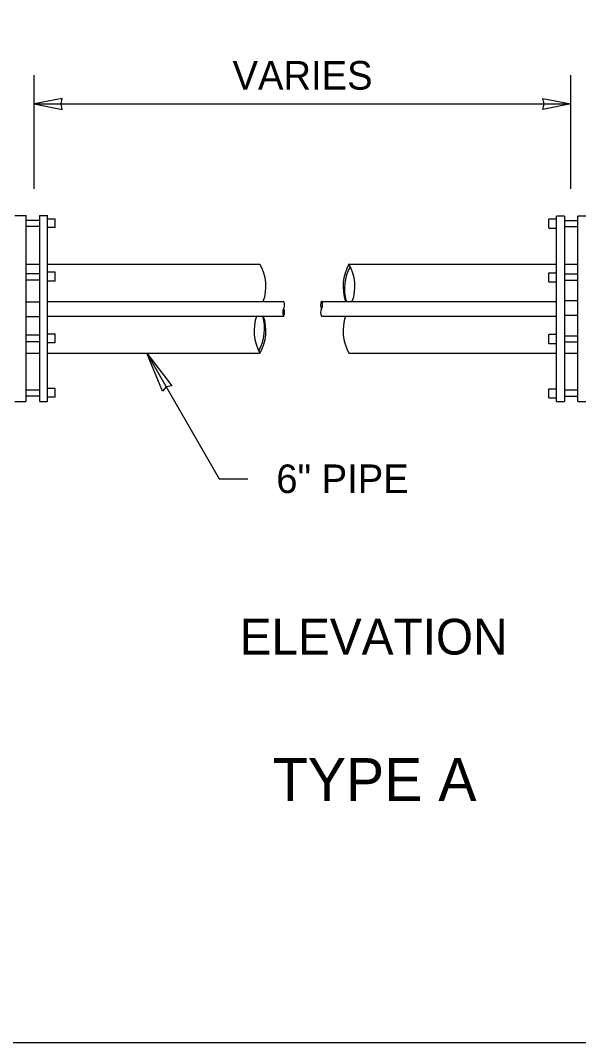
# Model space of a CAD drawing. Extents: x 99862 to 103151, y 100000 to 102076.
# Drawn here: x 100475 to 100788, y 100000 to 100572 of the extents above; entities that cross this region are included whole.
import ezdxf

# ---------------------------------------------------------------- set-up
doc = ezdxf.new("R2010")
doc.units = 0
for name, color, linetype in [('Level 1', 7, 'Continuous'), ('Level 15', 7, 'Continuous'), ('Level 18', 7, 'Continuous'), ('Level 20', 7, 'Continuous'), ('Level 6', 7, 'Continuous')]:
    doc.layers.add(name, color=color, linetype=linetype)

msp = doc.modelspace()

# ---------------------------------------------------------------- linework, layer by layer
at = {"layer": 'Level 1'}
msp.add_lwpolyline([(99862, 99999.5), (103151, 99999.5), (103151, 102075.5), (99862, 102075.5)], close=True, dxfattribs=at)
at = {"layer": 'Level 15'}
for p, q in [((100483.01, 100477.71), (100483.01, 100541.21)), ((100783.78, 100477.71), (100783.78, 100541.21)), ((100483.01, 100525.21), (100783.78, 100525.21)), ((100546.06, 100385.62), (100586.68, 100315.26)), ((100586.68, 100315.26), (100602.68, 100315.26))]:
    msp.add_line(p, q, dxfattribs=at)
for points in [[(100483.01, 100525.21), (100498.73, 100522.13), (100498, 100525.21), (100498.73, 100528.29)], [(100783.78, 100525.21), (100768.06, 100522.13), (100768.79, 100525.21), (100768.06, 100528.29)], [(100546.06, 100385.62), (100560.06, 100367.34), (100556.94, 100366.77), (100554.89, 100364.36)]]:
    msp.add_lwpolyline(points, close=True, dxfattribs=at)
at = {"layer": 'Level 18'}
for p, q in [((100472.06, 100462.71), (100478.43, 100462.71)), ((100478.43, 100358.76), (100478.43, 100462.71)), ((100478.43, 100460.16), (100485.89, 100460.16)), ((100485.89, 100462.71), (100485.89, 100358.76)), ((100485.89, 100462.71), (100490.41, 100462.71)), ((100490.41, 100358.76), (100490.41, 100462.71)), ((100490.41, 100460.9), (100494.66, 100460.9)), ((100494.66, 100455.92), (100494.66, 100460.9)), ((100775.52, 100460.58), (100771.41, 100460.58)), ((100771.41, 100455.62), (100771.41, 100460.58)), ((100775.67, 100358.46), (100775.67, 100462.4)), ((100780.17, 100462.4), (100775.67, 100462.4)), ((100780.17, 100462.4), (100780.17, 100358.46)), ((100780.17, 100459.87), (100787.63, 100459.87)), ((100787.63, 100358.46), (100787.63, 100462.4)), ((100794.02, 100462.4), (100787.63, 100462.4)), ((100478.43, 100456.67), (100485.89, 100456.67)), ((100494.66, 100455.92), (100490.41, 100455.92)), ((100771.41, 100455.62), (100775.52, 100455.62)), ((100787.63, 100456.36), (100780.17, 100456.36)), ((100478.43, 100430.18), (100485.89, 100430.18)), ((100478.43, 100426.7), (100485.89, 100426.7)), ((100494.66, 100430.88), (100490.56, 100430.88)), ((100494.66, 100425.92), (100490.56, 100425.92)), ((100494.66, 100425.92), (100494.66, 100430.88)), ((100771.41, 100430.58), (100775.52, 100430.58)), ((100771.41, 100425.61), (100771.41, 100430.58)), ((100771.41, 100425.61), (100775.52, 100425.61)), ((100787.63, 100429.87), (100780.17, 100429.87)), ((100787.63, 100426.38), (100780.17, 100426.38)), ((100478.43, 100414.42), (100485.89, 100414.42)), ((100490.41, 100414.63), (100622.81, 100414.63)), ((100644.08, 100414.63), (100775.54, 100414.63)), ((100787.63, 100414.88), (100780.21, 100414.88)), ((100478.43, 100406.18), (100485.89, 100406.18)), ((100490.41, 100406.41), (100622.81, 100406.41)), ((100644.08, 100406.41), (100775.54, 100406.41)), ((100787.63, 100406.65), (100780.21, 100406.65)), ((100485.89, 100395.65), (100478.43, 100395.65)), ((100478.43, 100392.12), (100485.89, 100392.12)), ((100490.41, 100396.35), (100494.69, 100396.35)), ((100494.69, 100391.38), (100490.41, 100391.38)), ((100494.69, 100391.38), (100494.69, 100396.35)), ((100775.67, 100396.05), (100771.38, 100396.05)), ((100771.38, 100391.07), (100771.38, 100396.05)), ((100771.38, 100391.07), (100775.67, 100391.07)), ((100780.17, 100395.33), (100787.63, 100395.33)), ((100787.63, 100391.82), (100780.17, 100391.82)), ((100478.43, 100365.11), (100485.89, 100365.11)), ((100494.69, 100365.86), (100490.41, 100365.86)), ((100494.69, 100360.88), (100494.69, 100365.86)), ((100771.38, 100365.55), (100775.67, 100365.55)), ((100771.38, 100360.58), (100771.38, 100365.55)), ((100787.63, 100364.81), (100780.17, 100364.81)), ((100472.06, 100358.61), (100478.43, 100358.61)), ((100478.43, 100361.66), (100485.89, 100361.66)), ((100485.89, 100358.61), (100490.41, 100358.61)), ((100494.69, 100360.88), (100490.41, 100360.88)), ((100771.38, 100360.58), (100775.67, 100360.58)), ((100780.17, 100358.3), (100775.67, 100358.3)), ((100787.63, 100361.35), (100780.17, 100361.35)), ((100794.02, 100358.3), (100787.63, 100358.3))]:
    msp.add_line(p, q, dxfattribs=at)
for centre, start, end in [((100619.24, 100412.58), 330, 30), ((100647.64, 100412.58), 150, 210), ((100640.52, 100412.58), 330, 30), ((100626.37, 100408.47), 150, 210), ((100619.24, 100408.47), 330, 30), ((100647.64, 100408.47), 150, 210)]:
    msp.add_arc(centre, 4.11, start, end, dxfattribs=at)
at = {"layer": 'Level 6'}
for p, q in [((100478.43, 100435.38), (100485.89, 100435.38)), ((100490.41, 100435.38), (100609.5, 100435.38)), ((100659.4, 100435.38), (100775.52, 100435.38)), ((100780.17, 100435.38), (100787.63, 100435.38)), ((100478.43, 100385.62), (100485.89, 100385.62)), ((100490.41, 100385.62), (100609.5, 100385.62)), ((100659.4, 100385.62), (100775.67, 100385.62)), ((100780.17, 100385.62), (100787.63, 100385.62))]:
    msp.add_line(p, q, dxfattribs=at)
for centre, radius, start, end in [((100587.98, 100422.96), 24.85, 340.4269, 30), ((100680.92, 100422.96), 24.85, 150, 199.5731), ((100682.74, 100421.62), 25.84, 151.1758, 195.6878), ((100637.88, 100422.96), 24.85, 340.4269, 30), ((100631.03, 100398.11), 24.85, 160.488, 210), ((100587.45, 100399.33), 24.66, 329.9768, 16.6845), ((100587.98, 100398.11), 24.85, 330, 19.512), ((100680.92, 100398.11), 24.85, 160.488, 210)]:
    msp.add_arc(centre, radius, start, end, dxfattribs=at)

# ---------------------------------------------------------------- texts
at = {"layer": 'Level 20'}
for s, height, p in [('VARIES', 16, (100594.15, 100533.21)), ('6" PIPE', 16, (100618.68, 100307.26)), ('ELEVATION', 20, (100598.15, 100216.82)), ('TYPE A', 24, (100616.75, 100134.82))]:
    msp.add_text(s, height=height, dxfattribs=at).set_placement(p)

doc.saveas('drawing.dxf')
